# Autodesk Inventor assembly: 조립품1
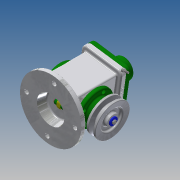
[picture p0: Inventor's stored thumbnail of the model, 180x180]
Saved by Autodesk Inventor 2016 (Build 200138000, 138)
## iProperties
Created: 2018-10
Part Number: 조립품1
Document SubType Name: Assembly
Designer: Administrator
Author: Administrator
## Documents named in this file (18)
- Y:\481007V1016 홍진욱\조립품1.iam
- Y:\481007V1016 홍진욱\E-링.ipt
- Y:\481007V1016 홍진욱\V-벨트풀리.ipt
- Y:\481007V1016 홍진욱\덮개.ipt
- Y:\481007V1016 홍진욱\뒤커버.ipt
- Y:\481007V1016 홍진욱\링크.ipt
- Y:\481007V1016 홍진욱\베어링 17 x 40 x 12.ipt
- Y:\481007V1016 홍진욱\본체.ipt
- Y:\481007V1016 홍진욱\볼트 M4 x 8.ipt
- Y:\481007V1016 홍진욱\볼트 M4 x 10.ipt
- Y:\481007V1016 홍진욱\슬라이더.ipt
- Y:\481007V1016 홍진욱\앞커버.ipt
- Y:\481007V1016 홍진욱\오일 실 17 30 8.ipt
- Y:\481007V1016 홍진욱\와셔 4x16.ipt
- Y:\481007V1016 홍진욱\클레비스 핀 6 x 22.ipt
- 클레비스 핀 6 x 22.ipt
- Y:\481007V1016 홍진욱\키 4 x 4 x 12.ipt
- Y:\481007V1016 홍진욱\편심축.ipt
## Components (2 placed, 2 different names)
1. E-링:1
2. V-벨트풀리:1
